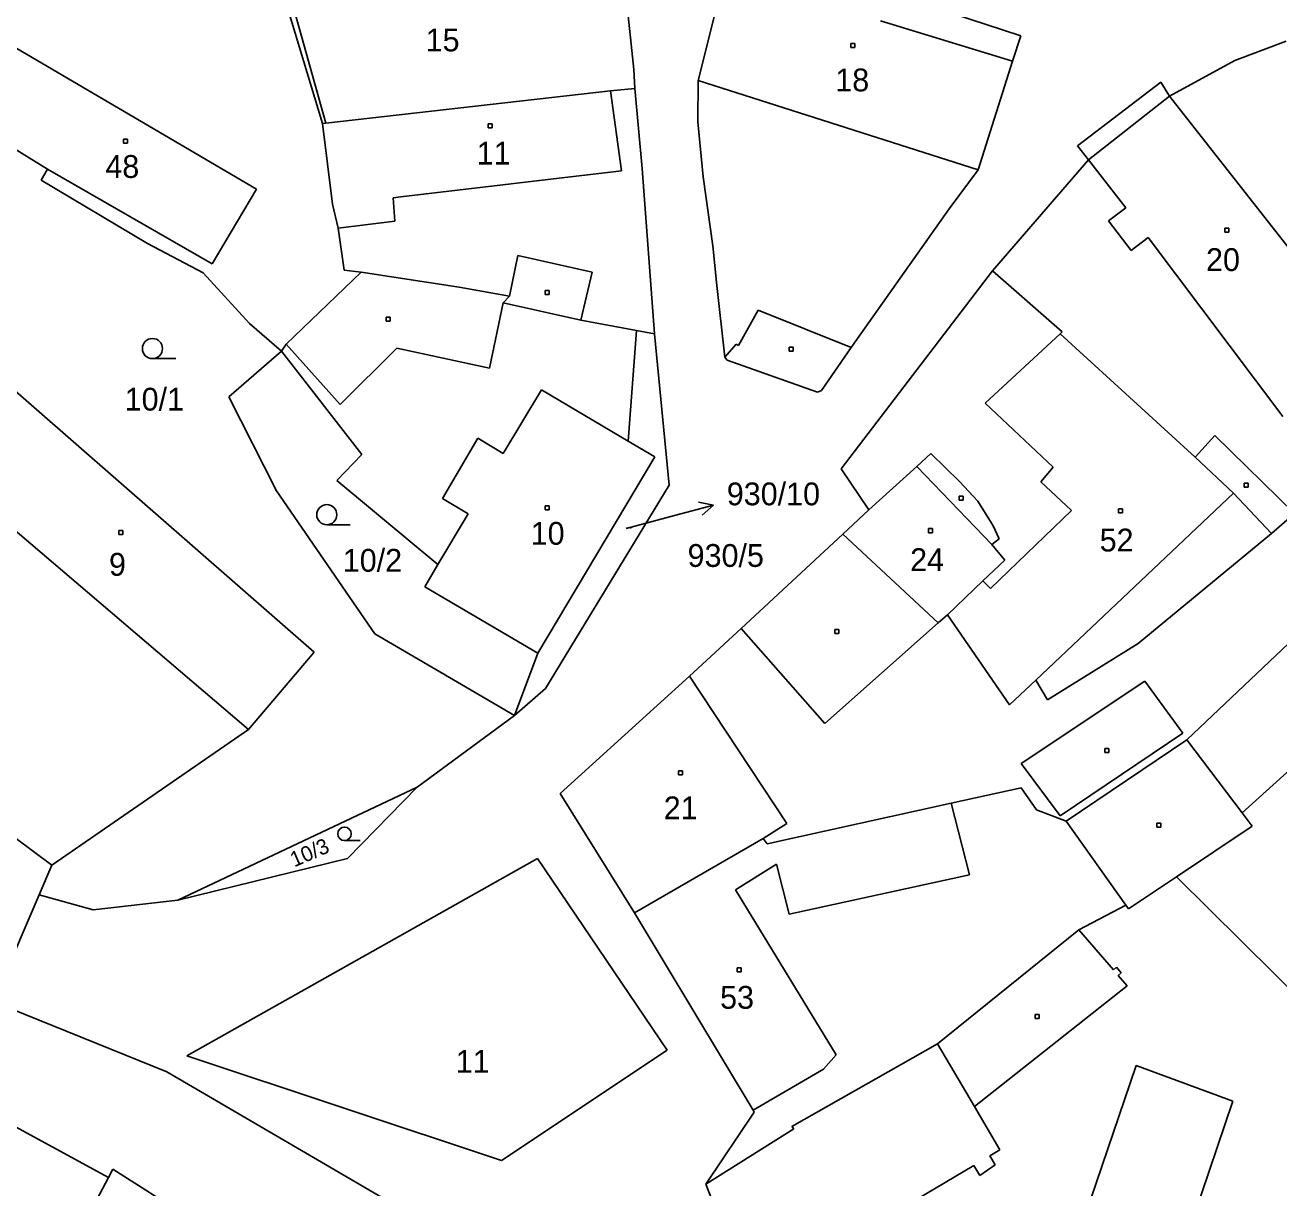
# Model space of a CAD drawing. Extents: x -796130 to -793145, y -1109506 to -1106267.
# Drawn here: x -794591.8 to -794498.3, y -1107676.5 to -1107589.9 of the extents above; entities that cross this region are included whole.
import ezdxf

# ---------------------------------------------------------------- set-up
doc = ezdxf.new("R2010")
doc.units = 0
for name, color, linetype in [('Komunikace', 7, 'Continuous'), ('Vrstva 1', 7, 'Continuous'), ('Vrstva 14', 7, 'Continuous'), ('Vrstva 15', 7, 'Continuous'), ('Vrstva 16', 7, 'Continuous'), ('Vrstva 2', 7, 'Continuous'), ('Vrstva 23', 7, 'Continuous'), ('Vrstva 25', 7, 'Continuous')]:
    doc.layers.add(name, color=color, linetype=linetype)

msp = doc.modelspace()

# ---------------------------------------------------------------- linework, layer by layer
at = {"layer": 'Komunikace'}
msp.add_line((-794546.96, -1107627.38), (-794543.37, -1107626.42), dxfattribs=at)
at = {"layer": 'Vrstva 1'}
for p, q in [((-794573.71, -1107581.57), (-794569.36, -1107597.17)), ((-794546.4, -1107593.16), (-794547.46, -1107582.9)), ((-794541.61, -1107593.99), (-794539.19, -1107584.36)), ((-794526.84, -1107587.61), (-794517.54, -1107590.65)), ((-794518.17, -1107592.56), (-794517.54, -1107590.65)), ((-794497.77, -1107591.05), (-794501.58, -1107592.5)), ((-794520.72, -1107600.65), (-794518.17, -1107592.56)), ((-794501.58, -1107592.5), (-794506.46, -1107595.16)), ((-794546.32, -1107594.59), (-794546.4, -1107593.16)), ((-794541.63, -1107597.07), (-794541.61, -1107593.99)), ((-794569.36, -1107597.17), (-794548.14, -1107594.76)), ((-794548.14, -1107594.76), (-794546.32, -1107594.59)), ((-794546.32, -1107594.59), (-794545.77, -1107600.55)), ((-794513.33, -1107598.86), (-794507.12, -1107594.11)), ((-794507.12, -1107594.11), (-794506.46, -1107595.16)), ((-794506.46, -1107595.16), (-794491.75, -1107613.89)), ((-794456.16, -1107596.58), (-794505.16, -1107643.13)), ((-794596.1, -1107596.92), (-794590.11, -1107600.59)), ((-794569.61, -1107597.2), (-794569.36, -1107597.17)), ((-794568.86, -1107603.21), (-794569.61, -1107597.2)), ((-794541.22, -1107601.17), (-794541.63, -1107597.07)), ((-794512.5, -1107599.89), (-794513.33, -1107598.86)), ((-794545.77, -1107600.55), (-794544.85, -1107612.87)), ((-794512.5, -1107599.89), (-794519.65, -1107608.18)), ((-794590.11, -1107600.59), (-794590.58, -1107601.43)), ((-794590.58, -1107601.43), (-794582.67, -1107606.13)), ((-794540.52, -1107606.31), (-794541.22, -1107601.17)), ((-794522.9, -1107603.56), (-794520.72, -1107600.65)), ((-794568.45, -1107605), (-794568.86, -1107603.21)), ((-794530.2, -1107613.88), (-794522.9, -1107603.56)), ((-794567.99, -1107608.13), (-794568.45, -1107605)), ((-794582.67, -1107606.13), (-794578.5, -1107608.32)), ((-794540.21, -1107609.27), (-794540.52, -1107606.31)), ((-794578.5, -1107608.32), (-794575.06, -1107612.09)), ((-794572.32, -1107613.64), (-794566.74, -1107608.27)), ((-794566.74, -1107608.27), (-794567.99, -1107608.13)), ((-794566.74, -1107608.27), (-794559.43, -1107609.39)), ((-794519.65, -1107608.18), (-794530.94, -1107622.94)), ((-794519.65, -1107608.18), (-794514.47, -1107612.72)), ((-794559.43, -1107609.39), (-794555.68, -1107610.07)), ((-794539.61, -1107614.62), (-794540.21, -1107609.27)), ((-794556.14, -1107610.55), (-794555.68, -1107610.07)), ((-794550.36, -1107611.85), (-794556.14, -1107610.55)), ((-794575.06, -1107612.09), (-794572.67, -1107614.17)), ((-794546.21, -1107612.62), (-794550.36, -1107611.85)), ((-794546.21, -1107612.62), (-794546.82, -1107620.86)), ((-794544.85, -1107612.87), (-794546.21, -1107612.62)), ((-794514.47, -1107612.72), (-794514.62, -1107612.86)), ((-794596.99, -1107613.22), (-794570.24, -1107636.6)), ((-794572.67, -1107614.17), (-794572.32, -1107613.64)), ((-794543.77, -1107624.16), (-794544.85, -1107612.87)), ((-794514.62, -1107612.86), (-794504.56, -1107622.05)), ((-794572.67, -1107614.17), (-794576.6, -1107617.56)), ((-794572.67, -1107614.17), (-794566.69, -1107621.87)), ((-794532.42, -1107617.1), (-794530.2, -1107613.88)), ((-794501.05, -1107648.58), (-794463.29, -1107614.43)), ((-794539.43, -1107614.84), (-794539.61, -1107614.62)), ((-794532.7, -1107617.22), (-794539.43, -1107614.84)), ((-794532.7, -1107617.22), (-794532.42, -1107617.1)), ((-794576.6, -1107617.56), (-794573.04, -1107624.56)), ((-794544.84, -1107622.03), (-794546.82, -1107620.86)), ((-794566.69, -1107621.87), (-794568.55, -1107623.8)), ((-794544.84, -1107622.03), (-794553.56, -1107636.67)), ((-794504.56, -1107622.05), (-794501.68, -1107624.75)), ((-794528.88, -1107625.99), (-794530.94, -1107622.94)), ((-794525.31, -1107622.75), (-794528.88, -1107625.99)), ((-794519.71, -1107628.57), (-794525.31, -1107622.75)), ((-794568.55, -1107623.8), (-794561.01, -1107630.07)), ((-794573.04, -1107624.56), (-794565.72, -1107635.23)), ((-794552.98, -1107639.29), (-794543.77, -1107624.16)), ((-794501.68, -1107624.75), (-794498.85, -1107627.74)), ((-794528.88, -1107625.99), (-794530.82, -1107627.79)), ((-794498.85, -1107627.74), (-794497.15, -1107626.26)), ((-794530.82, -1107627.79), (-794538.4, -1107634.82)), ((-794523.72, -1107634.42), (-794530.82, -1107627.79)), ((-794518.75, -1107629.74), (-794519.71, -1107628.57)), ((-794498.85, -1107627.74), (-794508.8, -1107635.96)), ((-794561.99, -1107631.72), (-794561.01, -1107630.07)), ((-794520.37, -1107631.28), (-794518.75, -1107629.74)), ((-794523.02, -1107633.8), (-794520.37, -1107631.28)), ((-794553.56, -1107636.67), (-794561.99, -1107631.72)), ((-794523.72, -1107634.42), (-794523.02, -1107633.8)), ((-794518.38, -1107640.52), (-794523.02, -1107633.8)), ((-794542.24, -1107638.39), (-794538.4, -1107634.82)), ((-794565.72, -1107635.23), (-794555.29, -1107641.32)), ((-794508.8, -1107635.96), (-794515.56, -1107640.14)), ((-794570.24, -1107636.6), (-794575.12, -1107642.36)), ((-794555.29, -1107641.32), (-794553.56, -1107636.67)), ((-794551.89, -1107647.13), (-794542.24, -1107638.39)), ((-794516.42, -1107638.67), (-794518.38, -1107640.52)), ((-794515.56, -1107640.14), (-794516.42, -1107638.67)), ((-794555.29, -1107641.32), (-794552.98, -1107639.29)), ((-794562.55, -1107646.65), (-794555.29, -1107641.32)), ((-794575.12, -1107642.36), (-794589.79, -1107652.47)), ((-794514.17, -1107649.2), (-794505.16, -1107643.13)), ((-794505.16, -1107643.13), (-794501.05, -1107648.58)), ((-794580.4, -1107655.07), (-794562.55, -1107646.65)), ((-794567.75, -1107651.97), (-794562.55, -1107646.65)), ((-794546.36, -1107656.03), (-794551.89, -1107647.13)), ((-794517.53, -1107646.7), (-794522.73, -1107647.84)), ((-794517.53, -1107646.7), (-794516.37, -1107648.35)), ((-794522.73, -1107647.84), (-794536.47, -1107650.87)), ((-794516.37, -1107648.35), (-794514.17, -1107649.2)), ((-794501.05, -1107648.58), (-794500.3, -1107649.57)), ((-794500.3, -1107649.57), (-794505.95, -1107653.34)), ((-794536.76, -1107650.49), (-794546.36, -1107656.03)), ((-794536.47, -1107650.87), (-794536.76, -1107650.49)), ((-794580.4, -1107655.07), (-794567.75, -1107651.97)), ((-794579.73, -1107666.67), (-794553.58, -1107651.98)), ((-794553.58, -1107651.98), (-794543.92, -1107666.26)), ((-794589.79, -1107652.47), (-794590.74, -1107654.68)), ((-794505.95, -1107653.34), (-794509.53, -1107655.72)), ((-794505.95, -1107653.34), (-794489.99, -1107669.12)), ((-794590.74, -1107654.68), (-794593.72, -1107661.58)), ((-794590.74, -1107654.68), (-794586.72, -1107655.81)), ((-794586.72, -1107655.81), (-794580.4, -1107655.07)), ((-794513.22, -1107657.29), (-794509.72, -1107655.45)), ((-794509.53, -1107655.72), (-794509.72, -1107655.45)), ((-794537.51, -1107670.74), (-794546.36, -1107656.03)), ((-794523.75, -1107665.79), (-794513.22, -1107657.29)), ((-794598.74, -1107660.82), (-794581.21, -1107667.86)), ((-794523.75, -1107665.79), (-794534.61, -1107671.95)), ((-794556.27, -1107674.47), (-794579.73, -1107666.67)), ((-794543.92, -1107666.26), (-794556.27, -1107674.47)), ((-794581.21, -1107667.86), (-794549.92, -1107686.13)), ((-794595.21, -1107670.52), (-794585.56, -1107675.74)), ((-794541.04, -1107676.25), (-794537.43, -1107670.87)), ((-794537.43, -1107670.87), (-794537.51, -1107670.74)), ((-794534.46, -1107672.11), (-794541.04, -1107676.25)), ((-794534.61, -1107671.95), (-794534.46, -1107672.11)), ((-794585.23, -1107675.12), (-794585.56, -1107675.74)), ((-794577.55, -1107680), (-794585.23, -1107675.12)), ((-794585.56, -1107675.74), (-794595.94, -1107695.24)), ((-794541.04, -1107676.25), (-794532.44, -1107698.06))]:
    msp.add_line(p, q, dxfattribs=at)
at = {"layer": 'Vrstva 16'}
for p, q in [((-794543.37, -1107626.42), (-794540.471, -1107625.647)), ((-794540.471, -1107625.647), (-794541.566, -1107625.421)), ((-794540.471, -1107625.647), (-794541.308, -1107626.387))]:
    msp.add_line(p, q, dxfattribs=at)
at = {"layer": 'Vrstva 2'}
for p, q in [((-794569.61, -1107597.2), (-794574.29, -1107581.74)), ((-794518.17, -1107592.56), (-794528, -1107589.55)), ((-794592.83, -1107591.35), (-794574.52, -1107602.08)), ((-794541.61, -1107593.99), (-794520.72, -1107600.65)), ((-794547.31, -1107600.73), (-794548.14, -1107594.76)), ((-794512.5, -1107599.89), (-794506.46, -1107595.16)), ((-794509.73, -1107603.47), (-794512.5, -1107599.89)), ((-794577.83, -1107607.66), (-794590.11, -1107600.59)), ((-794547.31, -1107600.73), (-794563.78, -1107602.67)), ((-794574.52, -1107602.08), (-794577.83, -1107607.66)), ((-794563.78, -1107602.67), (-794564.34, -1107602.74)), ((-794564.34, -1107602.74), (-794564.23, -1107604.48)), ((-794511, -1107604.45), (-794509.73, -1107603.47)), ((-794564.23, -1107604.48), (-794568.45, -1107605)), ((-794509.33, -1107606.66), (-794511, -1107604.45)), ((-794508.05, -1107605.7), (-794509.33, -1107606.66)), ((-794498.01, -1107619.02), (-794508.05, -1107605.7)), ((-794555.05, -1107607.03), (-794555.68, -1107610.07)), ((-794555.05, -1107607.03), (-794549.5, -1107608.28)), ((-794549.5, -1107608.28), (-794550.36, -1107611.85)), ((-794557.15, -1107615.43), (-794556.14, -1107610.55)), ((-794538.59, -1107613.75), (-794537.14, -1107611.11)), ((-794537.14, -1107611.11), (-794530.2, -1107613.88)), ((-794568.3, -1107618.14), (-794572.32, -1107613.64)), ((-794539.61, -1107614.62), (-794538.78, -1107613.64)), ((-794538.78, -1107613.64), (-794538.59, -1107613.75)), ((-794520.2, -1107618.03), (-794514.62, -1107612.86)), ((-794564.07, -1107613.93), (-794568.3, -1107618.14)), ((-794557.15, -1107615.43), (-794564.07, -1107613.93)), ((-794556.14, -1107621.79), (-794553.29, -1107617.04)), ((-794546.82, -1107620.86), (-794553.29, -1107617.04)), ((-794515.14, -1107622.81), (-794520.2, -1107618.03)), ((-794560.66, -1107625.14), (-794558.03, -1107620.65)), ((-794558.03, -1107620.65), (-794556.14, -1107621.79)), ((-794503.08, -1107620.45), (-794504.56, -1107622.05)), ((-794497.15, -1107626.26), (-794503.08, -1107620.45)), ((-794524.26, -1107621.8), (-794525.31, -1107622.75)), ((-794522.12, -1107623.87), (-794524.26, -1107621.8)), ((-794516.05, -1107623.89), (-794515.14, -1107622.81)), ((-794520.75, -1107625.34), (-794522.12, -1107623.87)), ((-794513.78, -1107626.03), (-794516.05, -1107623.89)), ((-794596.64, -1107624.02), (-794575.12, -1107642.36)), ((-794516.42, -1107638.67), (-794501.68, -1107624.75)), ((-794558.75, -1107626.28), (-794560.66, -1107625.14)), ((-794519.6, -1107627.19), (-794520.75, -1107625.34)), ((-794561.01, -1107630.07), (-794558.75, -1107626.28)), ((-794519.82, -1107631.85), (-794513.78, -1107626.03)), ((-794519.15, -1107628.16), (-794519.6, -1107627.19)), ((-794519.71, -1107628.57), (-794519.15, -1107628.16)), ((-794520.37, -1107631.28), (-794519.82, -1107631.85)), ((-794532.15, -1107641.92), (-794538.4, -1107634.82)), ((-794523.72, -1107634.42), (-794532.15, -1107641.92)), ((-794534.99, -1107649.37), (-794542.24, -1107638.39)), ((-794508.3, -1107638.76), (-794517.51, -1107644.9)), ((-794505.48, -1107642.64), (-794508.3, -1107638.76)), ((-794505.48, -1107642.64), (-794514.62, -1107648.79)), ((-794514.62, -1107648.79), (-794517.51, -1107644.9)), ((-794589.79, -1107652.47), (-794596.99, -1107647.11)), ((-794521.38, -1107653.19), (-794522.73, -1107647.84)), ((-794536.76, -1107650.49), (-794534.99, -1107649.37)), ((-794509.72, -1107655.45), (-794514.17, -1107649.2)), ((-794538.81, -1107654.31), (-794535.76, -1107652.4)), ((-794535.76, -1107652.4), (-794534.82, -1107656.13)), ((-794534.82, -1107656.13), (-794521.38, -1107653.19)), ((-794531.32, -1107666.61), (-794538.81, -1107654.31)), ((-794513.22, -1107657.29), (-794510.65, -1107660.28)), ((-794510.65, -1107660.28), (-794510.42, -1107660.08)), ((-794510.42, -1107660.08), (-794510.06, -1107660.5)), ((-794510.06, -1107660.5), (-794510.29, -1107660.69)), ((-794510.29, -1107660.69), (-794509.62, -1107661.47)), ((-794509.62, -1107661.47), (-794520.99, -1107670.46)), ((-794520.99, -1107670.46), (-794523.75, -1107665.79)), ((-794532.25, -1107667.67), (-794531.32, -1107666.61)), ((-794537.51, -1107670.74), (-794532.25, -1107667.67)), ((-794508.96, -1107667.39), (-794517.75, -1107693.26)), ((-794501.74, -1107670.05), (-794508.96, -1107667.39)), ((-794519.12, -1107673.69), (-794520.99, -1107670.46)), ((-794511.68, -1107699.45), (-794501.74, -1107670.05)), ((-794519.85, -1107674.12), (-794519.12, -1107673.69)), ((-794519.45, -1107674.8), (-794519.85, -1107674.12)), ((-794530.29, -1107680.31), (-794521.06, -1107674.84)), ((-794521.06, -1107674.84), (-794520.61, -1107675.59)), ((-794520.61, -1107675.59), (-794519.45, -1107674.8))]:
    msp.add_line(p, q, dxfattribs=at)
at = {"layer": 'Vrstva 23'}
for p, q in [((-794582.29, -1107614.72), (-794580.54, -1107614.72)), ((-794569.29, -1107627.1), (-794567.54, -1107627.1)), ((-794567.97, -1107650.64), (-794566.797, -1107650.64))]:
    msp.add_line(p, q, dxfattribs=at)
for centre, radius in [((-794582.29, -1107613.97), 0.75), ((-794569.29, -1107626.35), 0.75), ((-794567.97, -1107650.137), 0.503)]:
    msp.add_circle(centre, radius, dxfattribs=at)
at = {"layer": 'Vrstva 25'}
for p, q in [((-794530.23, -1107591.22), (-794529.93, -1107591.22)), ((-794530.23, -1107591.52), (-794530.23, -1107591.22)), ((-794529.93, -1107591.22), (-794529.93, -1107591.52)), ((-794529.93, -1107591.52), (-794530.23, -1107591.52)), ((-794557.25, -1107597.21), (-794556.95, -1107597.21)), ((-794557.25, -1107597.51), (-794557.25, -1107597.21)), ((-794556.95, -1107597.51), (-794557.25, -1107597.51)), ((-794556.95, -1107597.21), (-794556.95, -1107597.51)), ((-794584.45, -1107598.35), (-794584.15, -1107598.35)), ((-794584.45, -1107598.65), (-794584.45, -1107598.35)), ((-794584.15, -1107598.65), (-794584.45, -1107598.65)), ((-794584.15, -1107598.35), (-794584.15, -1107598.65)), ((-794502.33, -1107605), (-794502.03, -1107605)), ((-794502.33, -1107605.3), (-794502.33, -1107605)), ((-794502.03, -1107605), (-794502.03, -1107605.3)), ((-794502.03, -1107605.3), (-794502.33, -1107605.3)), ((-794553, -1107609.63), (-794552.7, -1107609.63)), ((-794553, -1107609.93), (-794553, -1107609.63)), ((-794552.7, -1107609.93), (-794553, -1107609.93)), ((-794552.7, -1107609.63), (-794552.7, -1107609.93)), ((-794564.87, -1107611.62), (-794564.57, -1107611.62)), ((-794564.87, -1107611.92), (-794564.87, -1107611.62)), ((-794564.57, -1107611.62), (-794564.57, -1107611.92)), ((-794564.57, -1107611.92), (-794564.87, -1107611.92)), ((-794534.83, -1107613.86), (-794534.53, -1107613.86)), ((-794534.83, -1107614.16), (-794534.83, -1107613.86)), ((-794534.53, -1107614.16), (-794534.83, -1107614.16)), ((-794534.53, -1107613.86), (-794534.53, -1107614.16)), ((-794500.89, -1107624.01), (-794500.59, -1107624.01)), ((-794500.89, -1107624.31), (-794500.89, -1107624.01)), ((-794500.59, -1107624.31), (-794500.89, -1107624.31)), ((-794500.59, -1107624.01), (-794500.59, -1107624.31)), ((-794553, -1107625.68), (-794552.7, -1107625.68)), ((-794553, -1107625.98), (-794553, -1107625.68)), ((-794552.7, -1107625.68), (-794552.7, -1107625.98)), ((-794522.14, -1107624.97), (-794521.84, -1107624.97)), ((-794522.14, -1107625.27), (-794522.14, -1107624.97)), ((-794521.84, -1107625.27), (-794522.14, -1107625.27)), ((-794521.84, -1107624.97), (-794521.84, -1107625.27)), ((-794552.7, -1107625.98), (-794553, -1107625.98)), ((-794510.26, -1107625.9), (-794509.96, -1107625.9)), ((-794510.26, -1107626.2), (-794510.26, -1107625.9)), ((-794509.96, -1107626.2), (-794510.26, -1107626.2)), ((-794509.96, -1107625.9), (-794509.96, -1107626.2)), ((-794584.8, -1107627.53), (-794584.5, -1107627.53)), ((-794584.8, -1107627.83), (-794584.8, -1107627.53)), ((-794584.5, -1107627.53), (-794584.5, -1107627.83)), ((-794524.44, -1107627.39), (-794524.14, -1107627.39)), ((-794524.44, -1107627.69), (-794524.44, -1107627.39)), ((-794524.14, -1107627.69), (-794524.44, -1107627.69)), ((-794524.14, -1107627.39), (-794524.14, -1107627.69)), ((-794584.5, -1107627.83), (-794584.8, -1107627.83)), ((-794531.41, -1107634.91), (-794531.11, -1107634.91)), ((-794531.41, -1107635.21), (-794531.41, -1107634.91)), ((-794531.11, -1107634.91), (-794531.11, -1107635.21)), ((-794531.11, -1107635.21), (-794531.41, -1107635.21)), ((-794511.29, -1107643.78), (-794510.99, -1107643.78)), ((-794511.29, -1107644.08), (-794511.29, -1107643.78)), ((-794510.99, -1107644.08), (-794511.29, -1107644.08)), ((-794510.99, -1107643.78), (-794510.99, -1107644.08)), ((-794543.07, -1107645.43), (-794542.77, -1107645.43)), ((-794543.07, -1107645.73), (-794543.07, -1107645.43)), ((-794542.77, -1107645.43), (-794542.77, -1107645.73)), ((-794542.77, -1107645.73), (-794543.07, -1107645.73)), ((-794507.4, -1107649.34), (-794507.1, -1107649.34)), ((-794507.4, -1107649.64), (-794507.4, -1107649.34)), ((-794507.1, -1107649.64), (-794507.4, -1107649.64)), ((-794507.1, -1107649.34), (-794507.1, -1107649.64)), ((-794538.69, -1107660.12), (-794538.39, -1107660.12)), ((-794538.69, -1107660.42), (-794538.69, -1107660.12)), ((-794538.39, -1107660.12), (-794538.39, -1107660.42)), ((-794538.39, -1107660.42), (-794538.69, -1107660.42)), ((-794516.49, -1107663.59), (-794516.19, -1107663.59)), ((-794516.49, -1107663.89), (-794516.49, -1107663.59)), ((-794516.19, -1107663.89), (-794516.49, -1107663.89)), ((-794516.19, -1107663.59), (-794516.19, -1107663.89))]:
    msp.add_line(p, q, dxfattribs=at)

# ---------------------------------------------------------------- texts
at = {"layer": 'Vrstva 14'}
for s, height, p in [('15', 1.7, (-794561.92, -1107591.82)), ('10/1', 1.7, (-794584.36, -1107618.59)), ('930/10', 0.1, (-794546.96, -1107627.38)), ('930/5', 1.7, (-794542.39, -1107630.24)), ('10/2', 1.7, (-794568.1, -1107630.6)), ('11', 1.7, (-794559.68, -1107667.94))]:
    msp.add_text(s, height=height, dxfattribs=at).set_placement(p)
msp.add_text('10/3', height=1.14, rotation=23.42241, dxfattribs=at).set_placement((-794571.716, -1107652.639))
at = {"layer": 'Vrstva 15'}
for s, p in [('18', (-794531.38, -1107594.8)), ('11', (-794558.12, -1107600.26)), ('48', (-794585.8, -1107601.25)), ('20', (-794503.74, -1107608.19)), ('10', (-794554.09, -1107628.59)), ('52', (-794511.67, -1107629.09)), ('9', (-794585.53, -1107630.9)), ('24', (-794525.8, -1107630.55)), ('21', (-794544.17, -1107649.05)), ('53', (-794539.97, -1107663.17))]:
    msp.add_text(s, height=1.7, dxfattribs=at).set_placement(p)
at = {"layer": 'Vrstva 16'}
msp.add_text('930/10', height=1.7, dxfattribs=at).set_placement((-794539.47, -1107625.65))

doc.saveas('drawing.dxf')
